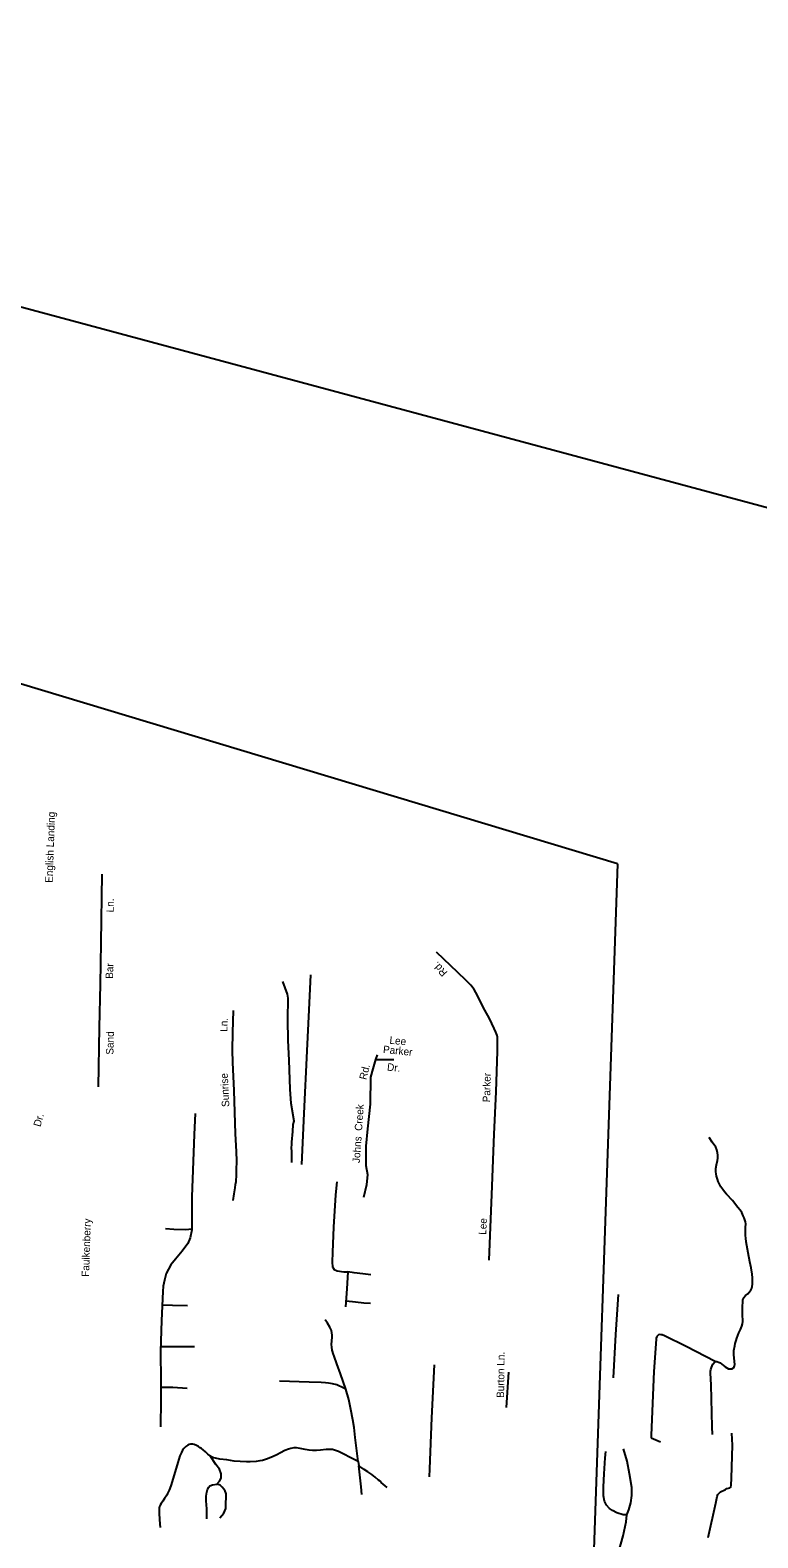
# Model space of a CAD drawing. Extents: x 2308163 to 2335412, y -96774 to 127732.
# Drawn here: x 2322537.4 to 2322562.4, y 95039.6 to 95091.3 of the extents above; entities that cross this region are included whole.
import ezdxf

# ---------------------------------------------------------------- set-up
doc = ezdxf.new("R2010")
doc.units = 0
for name, color, linetype in [('Old_Level_10', 7, 'Continuous'), ('Old_Level_35', 7, 'Continuous'), ('Old_Level_63', 7, 'Continuous')]:
    doc.layers.add(name, color=color, linetype=linetype)

msp = doc.modelspace()

# ---------------------------------------------------------------- linework, layer by layer
at = {"layer": 'Old_Level_35'}
for p, q in [((2322558.709, 95043.083), (2322558.705, 95042.994)), ((2322558.705, 95042.994), (2322559.03, 95042.862)), ((2322560.803, 95043.106), (2322560.796, 95043.372)), ((2322548.656, 95042.182), (2322548.676, 95042.033)), ((2322548.757, 95041.317), (2322548.676, 95042.033)), ((2322551.105, 95041.657), (2322551.116, 95041.929)), ((2322548.788, 95041.052), (2322548.757, 95041.317)), ((2322541.85, 95040.185), (2322541.865, 95039.921))]:
    msp.add_line(p, q, dxfattribs=at)
for points in [[(2322539.76, 95055.043), (2322539.793, 95057.073), (2322539.822, 95058.558), (2322539.848, 95059.979), (2322539.881, 95062.332)], [(2322553.147, 95049.085), (2322553.239, 95051.34), (2322553.321, 95053.409), (2322553.388, 95054.869), (2322553.437, 95056.259), (2322553.437, 95056.373), (2322553.437, 95056.513), (2322553.438, 95056.65), (2322553.434, 95056.743), (2322553.419, 95056.8), (2322553.383, 95056.91), (2322553.323, 95057.044), (2322553.159, 95057.376), (2322553.002, 95057.669), (2322552.696, 95058.278), (2322552.64, 95058.382), (2322552.523, 95058.525), (2322552.355, 95058.701), (2322552.08, 95058.958), (2322551.339, 95059.655)], [(2322546.38, 95052.443), (2322546.38, 95052.812), (2322546.377, 95052.96), (2322546.387, 95053.053), (2322546.389, 95053.14), (2322546.42, 95053.506), (2322546.435, 95053.74), (2322546.461, 95053.864), (2322546.366, 95054.469), (2322546.331, 95054.962), (2322546.293, 95055.956), (2322546.255, 95056.628), (2322546.241, 95057.348), (2322546.258, 95058.082), (2322546.23, 95058.216), (2322546.077, 95058.649)], [(2322546.721, 95052.375), (2322546.805, 95054.119), (2322546.913, 95056.273), (2322546.977, 95057.679), (2322547.03, 95058.881)], [(2322544.457, 95053.42), (2322544.407, 95054.914), (2322544.36, 95055.869), (2322544.347, 95056.292), (2322544.361, 95056.9), (2322544.387, 95057.659)], [(2322549.309, 95056.14), (2322549.253, 95055.973), (2322549.163, 95055.659), (2322549.084, 95055.365), (2322549.072, 95054.444), (2322548.983, 95053.595), (2322548.923, 95053.002), (2322548.92, 95052.339), (2322548.979, 95052.029), (2322548.947, 95051.674), (2322548.836, 95051.236)], [(2322549.253, 95055.973), (2322549.88, 95055.971)], [(2322543.068, 95054.123), (2322543.031, 95053.397), (2322542.958, 95051.261), (2322542.951, 95050.415), (2322542.95, 95050.137), (2322542.899, 95049.852), (2322542.813, 95049.663), (2322542.626, 95049.402), (2322542.394, 95049.121), (2322542.231, 95048.926), (2322542.078, 95048.637), (2322542.012, 95048.399), (2322541.967, 95048.203), (2322541.961, 95048.012), (2322541.913, 95047.016), (2322541.883, 95045.953), (2322541.893, 95044.951), (2322541.892, 95044.283), (2322541.883, 95043.37)], [(2322544.371, 95051.141), (2322544.407, 95051.366), (2322544.444, 95051.569), (2322544.454, 95051.685), (2322544.473, 95051.787), (2322544.486, 95052.021), (2322544.49, 95052.185), (2322544.499, 95052.488), (2322544.489, 95052.818), (2322544.457, 95053.42)], [(2322560.9, 95045.613), (2322560.925, 95045.613), (2322560.957, 95045.614), (2322561.011, 95045.596), (2322561.08, 95045.563), (2322561.126, 95045.522), (2322561.242, 95045.434), (2322561.303, 95045.392), (2322561.354, 95045.367), (2322561.417, 95045.36), (2322561.474, 95045.365), (2322561.523, 95045.396), (2322561.546, 95045.426), (2322561.562, 95045.467), (2322561.572, 95045.512), (2322561.54, 95045.841), (2322561.542, 95045.927), (2322561.544, 95045.989), (2322561.572, 95046.152), (2322561.589, 95046.23), (2322561.615, 95046.339), (2322561.641, 95046.416), (2322561.674, 95046.502), (2322561.715, 95046.603), (2322561.762, 95046.709), (2322561.814, 95046.827), (2322561.841, 95046.912), (2322561.849, 95046.982), (2322561.844, 95047.045), (2322561.839, 95047.178), (2322561.835, 95047.319), (2322561.839, 95047.506), (2322561.843, 95047.663), (2322561.852, 95047.724), (2322561.858, 95047.774), (2322561.88, 95047.814), (2322561.942, 95047.878), (2322562.014, 95047.939), (2322562.07, 95047.993), (2322562.118, 95048.062), (2322562.152, 95048.127), (2322562.172, 95048.19), (2322562.178, 95048.272), (2322562.179, 95048.357), (2322562.175, 95048.483), (2322562.163, 95048.608), (2322562.13, 95048.827), (2322562.086, 95049.032), (2322562.032, 95049.346), (2322561.962, 95049.723), (2322561.946, 95049.842), (2322561.937, 95049.935), (2322561.934, 95050.052), (2322561.943, 95050.215), (2322561.947, 95050.333), (2322561.94, 95050.403), (2322561.919, 95050.474), (2322561.893, 95050.539), (2322561.859, 95050.617), (2322561.809, 95050.721), (2322561.755, 95050.806), (2322561.679, 95050.902), (2322561.497, 95051.133), (2322561.291, 95051.357), (2322561.222, 95051.436), (2322561.162, 95051.517), (2322561.095, 95051.611), (2322561.047, 95051.695), (2322561.003, 95051.79), (2322560.976, 95051.864), (2322560.947, 95051.967), (2322560.932, 95052.054), (2322560.927, 95052.116), (2322560.926, 95052.234), (2322560.94, 95052.359), (2322560.975, 95052.514), (2322560.99, 95052.591), (2322560.993, 95052.696), (2322560.981, 95052.771), (2322560.952, 95052.881), (2322560.924, 95052.968), (2322560.795, 95053.143), (2322560.689, 95053.294)], [(2322547.932, 95051.782), (2322547.884, 95051.336), (2322547.815, 95050.221), (2322547.775, 95049.369), (2322547.763, 95049.024), (2322547.778, 95048.861), (2322547.836, 95048.767), (2322547.936, 95048.723), (2322548.169, 95048.695), (2322548.301, 95048.69)], [(2322542.95, 95050.158), (2322542.745, 95050.131), (2322542.335, 95050.145), (2322542.049, 95050.168)], [(2322548.301, 95048.69), (2322548.271, 95048.112), (2322548.229, 95047.484)], [(2322549.09, 95048.582), (2322548.817, 95048.621), (2322548.523, 95048.652), (2322548.301, 95048.69)], [(2322541.939, 95047.554), (2322542.287, 95047.55), (2322542.806, 95047.532)], [(2322548.243, 95047.691), (2322548.57, 95047.665), (2322548.854, 95047.625), (2322549.077, 95047.617)], [(2322557.418, 95045.057), (2322557.493, 95046.54), (2322557.581, 95047.914)], [(2322548.239, 95044.661), (2322548.057, 95045.19), (2322547.925, 95045.529), (2322547.831, 95045.794), (2322547.796, 95045.894), (2322547.779, 95045.963), (2322547.766, 95046.001), (2322547.75, 95046.104), (2322547.746, 95046.198), (2322547.755, 95046.323), (2322547.766, 95046.447), (2322547.769, 95046.517), (2322547.76, 95046.593), (2322547.741, 95046.675), (2322547.689, 95046.793), (2322547.606, 95046.928), (2322547.531, 95047.039)], [(2322560.9, 95045.613), (2322559.906, 95046.13), (2322559.164, 95046.492), (2322559.087, 95046.525), (2322559.048, 95046.534), (2322559.004, 95046.538), (2322558.956, 95046.525), (2322558.922, 95046.498), (2322558.899, 95046.467), (2322558.88, 95046.415), (2322558.88, 95046.382), (2322558.799, 95045.274), (2322558.709, 95043.083)], [(2322541.888, 95046.125), (2322542.238, 95046.13), (2322543.045, 95046.13)], [(2322551.116, 95041.929), (2322551.185, 95043.676), (2322551.27, 95045.502)], [(2322560.796, 95043.372), (2322560.757, 95044.812), (2322560.744, 95045.212), (2322560.744, 95045.282), (2322560.749, 95045.34), (2322560.772, 95045.414), (2322560.795, 95045.468), (2322560.821, 95045.522), (2322560.9, 95045.613)], [(2322553.744, 95044.032), (2322553.823, 95045.244)], [(2322542.79, 95044.69), (2322542.299, 95044.721), (2322541.893, 95044.725)], [(2322548.239, 95044.661), (2322548.1, 95044.728), (2322548, 95044.776), (2322547.922, 95044.809), (2322547.774, 95044.853), (2322547.642, 95044.872), (2322547.533, 95044.882), (2322547.385, 95044.894), (2322546.978, 95044.903), (2322545.964, 95044.937)], [(2322548.656, 95042.182), (2322548.551, 95043.012), (2322548.52, 95043.351), (2322548.48, 95043.608), (2322548.41, 95043.97), (2322548.333, 95044.316), (2322548.239, 95044.661)], [(2322560.662, 95039.578), (2322560.925, 95040.759), (2322560.965, 95040.985), (2322560.995, 95041.056), (2322561.042, 95041.108), (2322561.083, 95041.139), (2322561.123, 95041.161), (2322561.185, 95041.191), (2322561.249, 95041.221), (2322561.296, 95041.252), (2322561.313, 95041.254), (2322561.358, 95041.263), (2322561.403, 95041.281), (2322561.433, 95041.304), (2322561.445, 95041.373), (2322561.464, 95041.614), (2322561.488, 95042.74), (2322561.467, 95043.15)], [(2322543.426, 95042.512), (2322543.343, 95042.579), (2322543.281, 95042.624), (2322543.243, 95042.657), (2322543.189, 95042.697), (2322543.118, 95042.733), (2322543.034, 95042.763), (2322542.986, 95042.777), (2322542.91, 95042.782), (2322542.863, 95042.768), (2322542.815, 95042.746), (2322542.752, 95042.699), (2322542.679, 95042.631), (2322542.638, 95042.577), (2322542.595, 95042.488), (2322542.548, 95042.376), (2322542.473, 95042.144), (2322542.285, 95041.5), (2322542.234, 95041.345), (2322542.181, 95041.205), (2322542.121, 95041.082), (2322542.094, 95041.028), (2322542.021, 95040.913), (2322541.955, 95040.82), (2322541.907, 95040.742), (2322541.866, 95040.688), (2322541.85, 95040.642), (2322541.832, 95040.581), (2322541.831, 95040.527), (2322541.837, 95040.424), (2322541.85, 95040.185)], [(2322548.656, 95042.182), (2322548.41, 95042.314), (2322548.146, 95042.452), (2322547.985, 95042.527), (2322547.852, 95042.577), (2322547.775, 95042.595), (2322547.682, 95042.596), (2322547.564, 95042.591), (2322547.368, 95042.572), (2322547.227, 95042.566), (2322547.094, 95042.563), (2322546.977, 95042.574), (2322546.838, 95042.594), (2322546.673, 95042.629), (2322546.541, 95042.648), (2322546.447, 95042.65), (2322546.353, 95042.629), (2322546.275, 95042.607), (2322546.141, 95042.556), (2322545.998, 95042.481), (2322545.871, 95042.414), (2322545.745, 95042.354), (2322545.611, 95042.294), (2322545.516, 95042.258), (2322545.382, 95042.223), (2322545.288, 95042.208), (2322545.155, 95042.188), (2322544.958, 95042.176), (2322544.83, 95042.174), (2322544.608, 95042.182), (2322544.404, 95042.199), (2322544.154, 95042.236), (2322543.913, 95042.265), (2322543.766, 95042.293), (2322543.699, 95042.314), (2322543.634, 95042.342), (2322543.58, 95042.375), (2322543.504, 95042.431), (2322543.426, 95042.512)], [(2322543.917, 95040.248), (2322544.055, 95040.406), (2322544.117, 95040.57), (2322544.125, 95040.78), (2322544.134, 95040.927), (2322544.136, 95041.006), (2322544.135, 95041.07), (2322544.124, 95041.11), (2322544.096, 95041.169), (2322544.052, 95041.235), (2322543.992, 95041.307), (2322543.922, 95041.374), (2322543.808, 95041.405), (2322543.901, 95041.506), (2322543.964, 95041.617), (2322543.965, 95041.76), (2322543.907, 95041.925), (2322543.782, 95042.076), (2322543.58, 95042.375)], [(2322557.874, 95040.348), (2322557.742, 95040.352), (2322557.522, 95040.419), (2322557.378, 95040.498), (2322557.277, 95040.575), (2322557.177, 95040.682), (2322557.108, 95040.817), (2322557.071, 95041.01), (2322557.066, 95041.32), (2322557.096, 95041.761), (2322557.13, 95042.306), (2322557.154, 95042.528)], [(2322557.874, 95040.348), (2322557.939, 95040.523), (2322558.007, 95040.771), (2322558.045, 95041.021), (2322558.04, 95041.286), (2322557.967, 95041.761), (2322557.879, 95042.192), (2322557.757, 95042.618)], [(2322549.411, 95041.503), (2322549.36, 95041.548), (2322549.243, 95041.646), (2322549.13, 95041.733), (2322548.991, 95041.831), (2322548.861, 95041.912), (2322548.676, 95042.033)], [(2322543.468, 95040.214), (2322543.472, 95040.563), (2322543.45, 95040.833), (2322543.452, 95040.998), (2322543.465, 95041.132), (2322543.489, 95041.219), (2322543.533, 95041.298), (2322543.575, 95041.353), (2322543.662, 95041.387), (2322543.808, 95041.405)], [(2322549.656, 95041.297), (2322549.452, 95041.467), (2322549.411, 95041.503)], [(2322557.504, 95038.605), (2322557.562, 95038.987), (2322557.746, 95039.63), (2322557.851, 95040.113), (2322557.874, 95040.348)]]:
    msp.add_lwpolyline(points, dxfattribs=at)
at = {"layer": 'Old_Level_63'}
msp.add_line((2322557.553, 95062.69), (2322525.797, 95072.268), dxfattribs=at)
for points in [[(2322607.397, 95061.367), (2322597.076, 95065.645), (2322501.767, 95091.289)], [(2322557.553, 95062.69), (2322555.782, 95011.346), (2322523.73, 95012.357), (2322525.797, 95072.268)]]:
    msp.add_lwpolyline(points, dxfattribs=at)

# ---------------------------------------------------------------- texts
at = {"layer": 'Old_Level_10'}
for s, height, rotation, p in [('English Landing', 0.25632, 88.0247, (2322538.181, 95062.033)), ('Ln.', 0.2563, 89.0989, (2322540.275, 95061.022)), ('Bar', 0.2563, 88.1197, (2322540.251, 95058.74)), ('Rd.', 0.2563, 132.9634, (2322551.736, 95058.967)), ('Sand', 0.2563, 88.9158, (2322540.266, 95056.139)), ('Ln.', 0.2563, 88.0624, (2322544.17, 95056.923)), ('Parker', 0.2563, 354.2925, (2322549.501, 95056.2)), ('Lee', 0.2563, 354.2925, (2322549.723, 95056.518)), ('Dr.', 0.2563, 354.2925, (2322549.639, 95055.596)), ('Sunrise', 0.2563, 92.8193, (2322544.242, 95054.353)), ('Rd.', 0.2563, 76.1913, (2322548.938, 95055.262)), ('Parker', 0.2563, 88.7193, (2322553.182, 95054.505)), ('Johns  Creek ', 0.25632, 86.0484, (2322548.714, 95052.418)), ('Dr.', 0.2563, 74.2787, (2322537.763, 95053.648)), ('Faulkenberry', 0.25632, 88.1377, (2322539.43, 95048.517)), ('Lee', 0.2563, 86.8925, (2322553.045, 95049.956)), ('Burton Ln.', 0.2563, 89.2977, (2322553.66, 95044.363))]:
    msp.add_text(s, height=height, rotation=rotation, dxfattribs=at).set_placement(p)

doc.saveas('drawing.dxf')
